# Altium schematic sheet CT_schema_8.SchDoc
size 274 x 160 mm
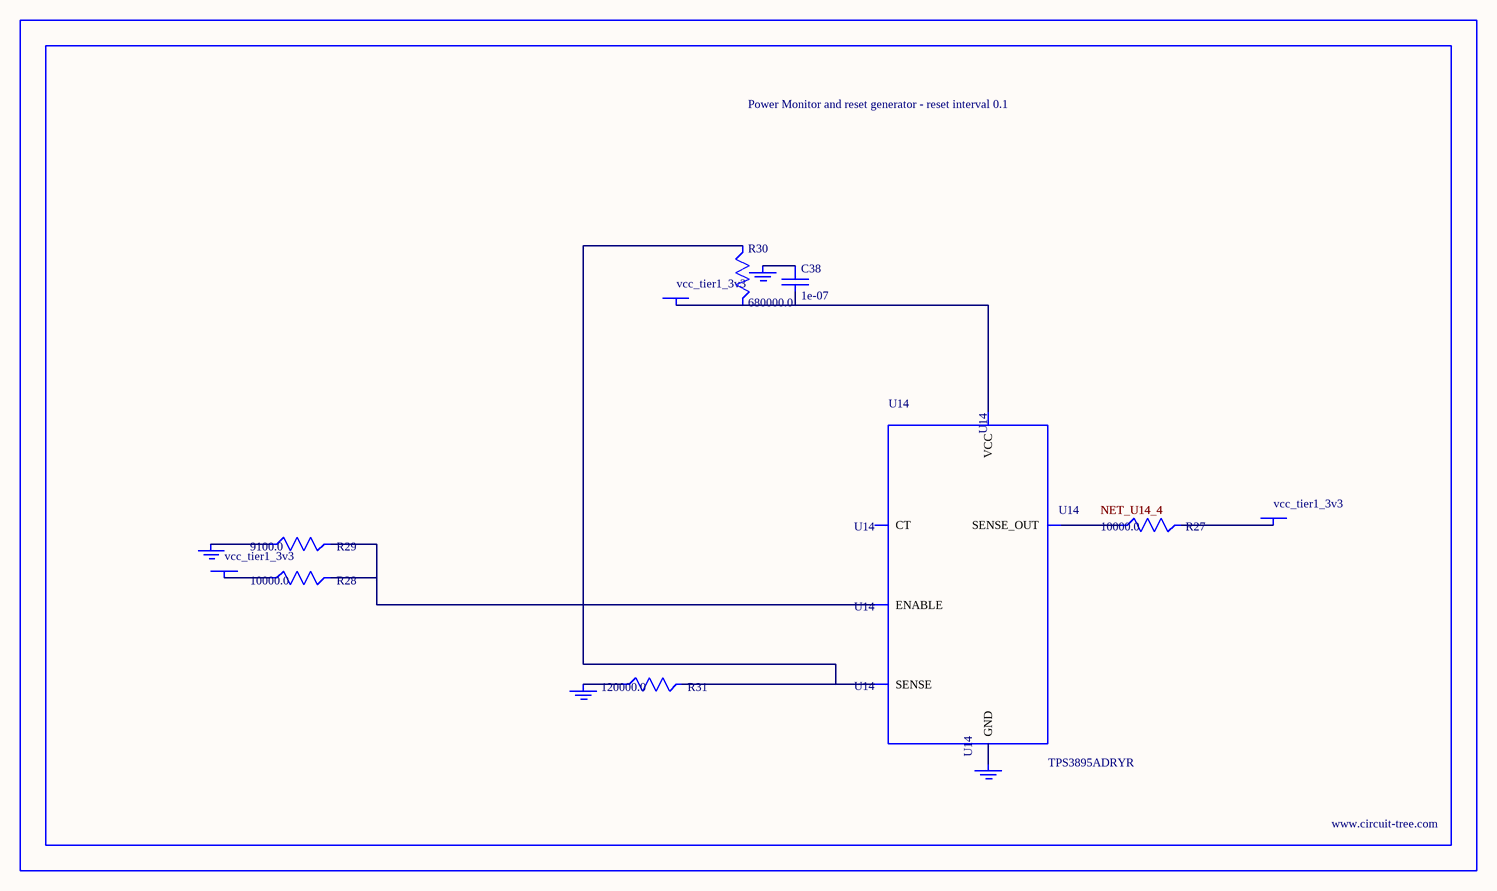
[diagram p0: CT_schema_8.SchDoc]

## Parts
BORDER7  (no value)
C38  1e-07  [C0402]
GND_INSTANCE_7_0  (no value)
GND_INSTANCE_7_1  (no value)
GND_INSTANCE_7_2  (no value)
GND_INSTANCE_7_3  (no value)
POWER_INSTANCE_7_0  vcc_tier1_3v3
POWER_INSTANCE_7_1  vcc_tier1_3v3
POWER_INSTANCE_7_2  vcc_tier1_3v3
R27  10000.0  [R0603]
R28  10000.0  [R0603]
R29  9100.0  [R0603]
R30  680000.0  [R0603]
R31  120000.0  [R0603]
U14  TPS3895ADRYR  [SON-6]

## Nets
NetC38_1: C38.1 GND_INSTANCE_7_2.0(GND)
NetC38_2: C38.2 POWER_INSTANCE_7_2.0(PWR) R30.2 U14.6(VCC)
NetGND_INSTANCE_7_0_0: GND_INSTANCE_7_0.0(GND) R29.1
NetGND_INSTANCE_7_1_0: GND_INSTANCE_7_1.0(GND) R31.1
NetGND_INSTANCE_7_3_0: GND_INSTANCE_7_3.0(GND) U14.2(GND)
NetPOWER_INSTANCE_7_0_0: POWER_INSTANCE_7_0.0(PWR) R28.1
NetPOWER_INSTANCE_7_1_0: POWER_INSTANCE_7_1.0(PWR) R27.2
NetR27_1: R27.1 U14.4(SENSE_OUT)
NetR28_2: R28.2 R29.2 U14.1(ENABLE)
NetR30_1: R30.1 R31.2 U14.3(SENSE)

Not connected (* = marked no-connect by the designer): U14 5(CT)

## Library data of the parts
BORDER7 = BORDER_PAGE7
C38 = C0402C104K3RACTU
GND_INSTANCE_7_0-GND_INSTANCE_7_3 = GND
POWER_INSTANCE_7_0-POWER_INSTANCE_7_2 = PWR
R27 R28 = RC0603JR-0710KL
R29 = RC0603JR-079K1L
R30 = RC0603JR-07680KL
R31 = RC0603JR-07120KL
